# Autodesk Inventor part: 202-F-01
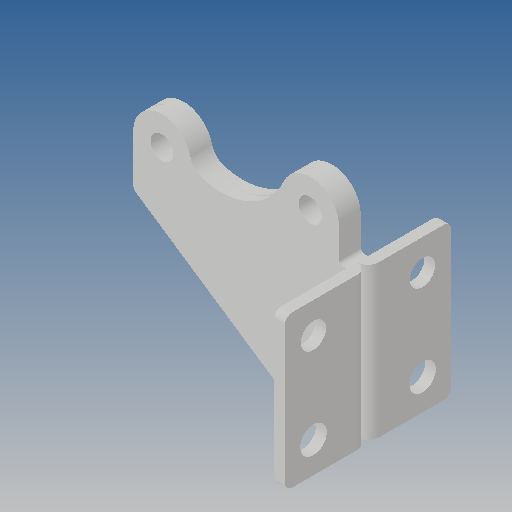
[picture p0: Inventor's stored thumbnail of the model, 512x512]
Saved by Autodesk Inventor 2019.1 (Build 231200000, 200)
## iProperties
Created: 2011-05
Part Number: 202-F-01
Material: Ogólny
Document SubType Name: Modeling
Designer: CADENGINEERING4
Density: 1 g/cm^3
Appearance: Domyślna
Author: CADENGINEERING4
Revision Number: ÈÎºÎ
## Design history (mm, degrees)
feature "Ô²½Ç1"
feature "¾µÏò1"
node "Bryła1"
node "Bryła2"
